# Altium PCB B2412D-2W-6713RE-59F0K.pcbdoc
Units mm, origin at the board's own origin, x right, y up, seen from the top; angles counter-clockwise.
Board outline 40 x 23 mm, 2 copper layers (Top Layer, Bottom Layer), stack 0.78 mm thick; 21 components, 12 nets, 48 pads, 26 vias.
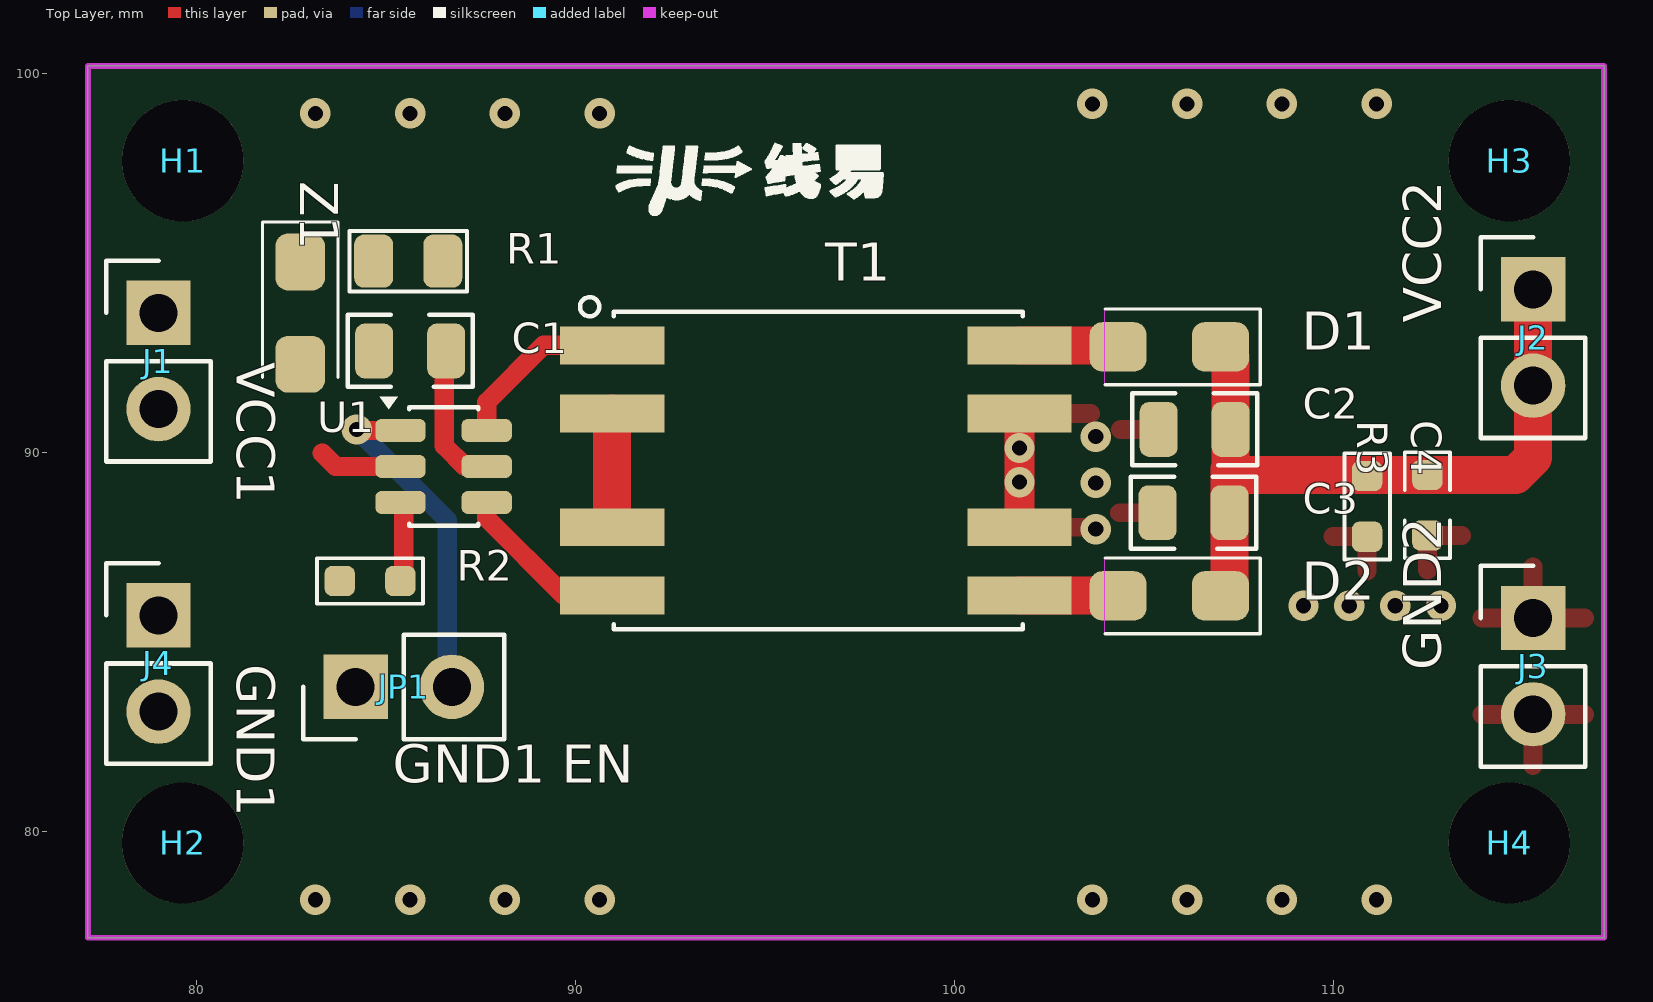
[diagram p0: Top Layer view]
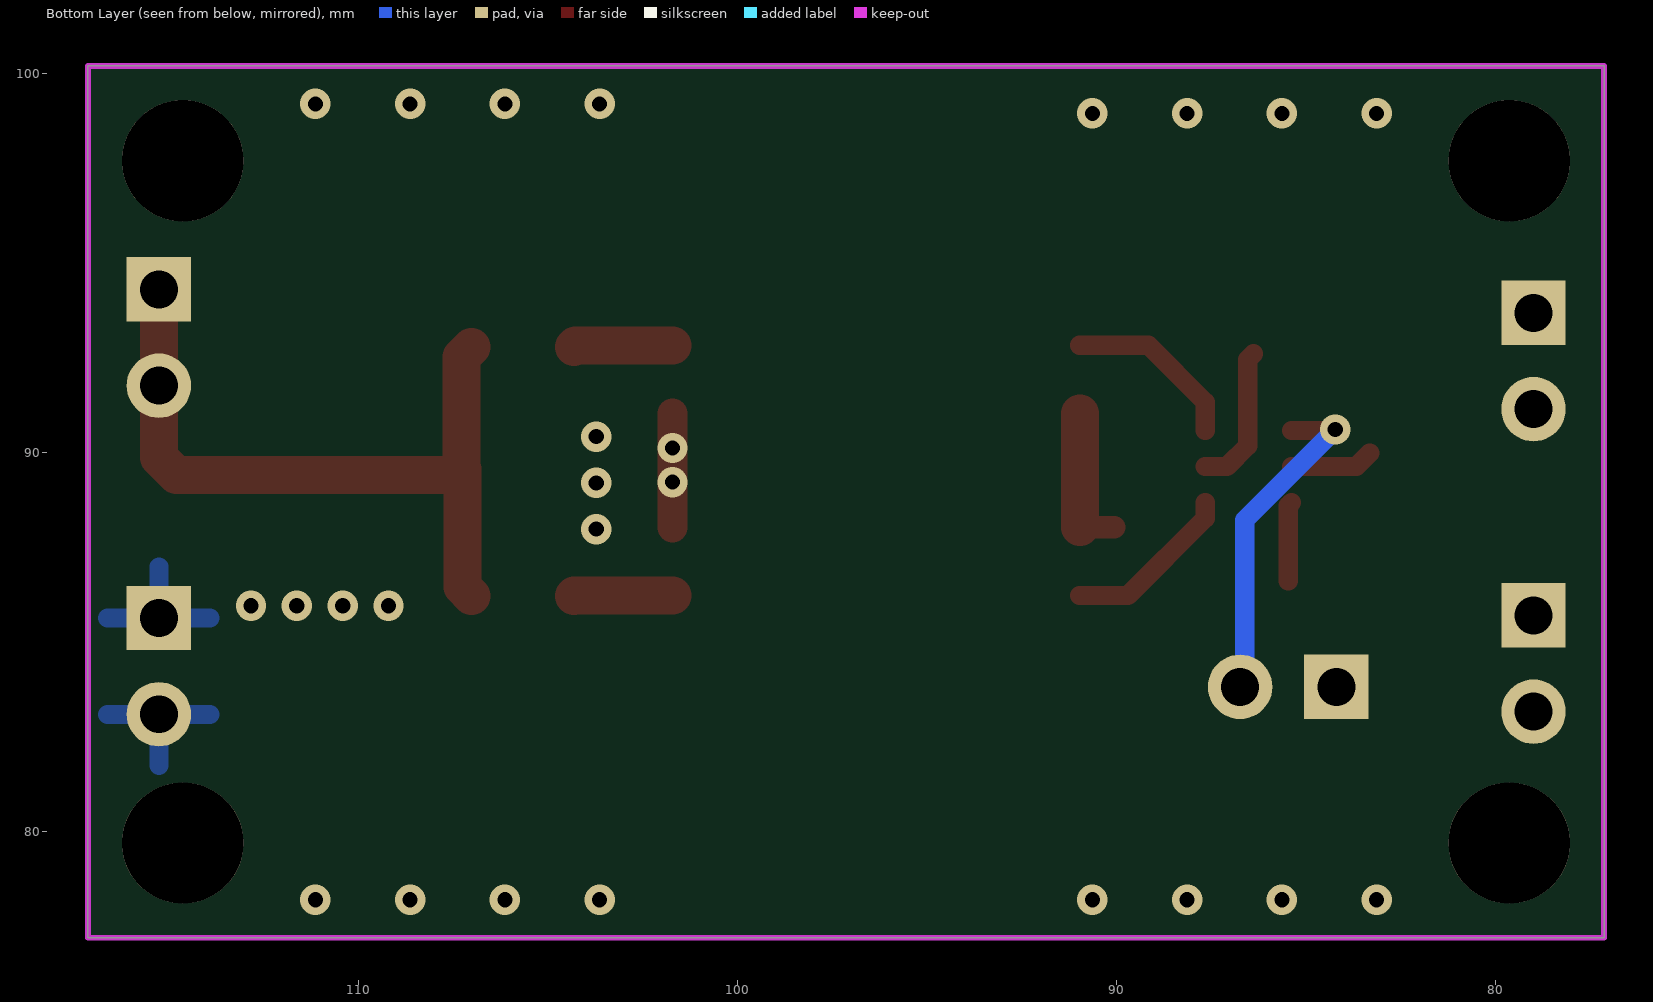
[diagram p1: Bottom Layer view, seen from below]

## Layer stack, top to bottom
Top Solder Mask Layer: solder mask 0.01, Dk 0
Top Layer: signal copper 0.035
dielectric 1: surface 0.71, FR4, Dk 4.5
Bottom Layer: signal copper 0.035
Bottom Solder Mask Layer: solder mask 0.01, Dk 0

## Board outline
117.15,100.2 117.15,77.2 77.15,77.2 77.15,100.2

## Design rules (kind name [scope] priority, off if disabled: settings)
BoardOutlineClearance copperThickness1oz [All] p0: genericclearance=0.254 ignorepadtopadclearanceinfootprint=FALSE except(0: Arc-SplitContinuation Track-SplitContinuation SMDPad-SplitContinuation THPad-SplitContinuation Via-SplitContinuation Fill-SplitContinuation Poly-SplitContinuation Region-SplitContinuation Text-SplitContinuation)
BoardOutlineClearance otherClearance [All] p0: genericclearance=0.254 ignorepadtopadclearanceinfootprint=FALSE except(0: Arc-SplitContinuation Track-SplitContinuation SMDPad-SplitContinuation THPad-SplitContinuation Via-SplitContinuation Fill-SplitContinuation Poly-SplitContinuation Region-SplitContinuation Text-SplitContinuation)
Clearance copperThickness1oz [All] p1: gap=0.178 ignorepadtopadclearanceinfootprint=FALSE
Clearance otherClearance [All] p1: gap=0.178 ignorepadtopadclearanceinfootprint=FALSE
DiffPairsRouting differentialPair [All] p1: maxuncoupledlength=10 minlimit=5 maxlimit=Infinity mostfreqgap=6 toplayer_minwidth=5 toplayer_prefwidth=100 toplayer_maxwidth=100 bottomlayer_minwidth=5 bottomlayer_prefwidth=100 bottomlayer_maxwidth=100
PasteMaskExpansion pasteMaskExpansion [All] p1: expansion=0
PlaneConnect innerPlane [All] p1: planeconnectstyle=Relief reliefexpansion=0.508 reliefentries=4 reliefconductorwidth=0.254 reliefairgap=0.254
PolygonConnect copper0 [All] p1: connectstyle=Direct reliefentries=4 reliefconductorwidth=10 polygonreliefangle="90 Angle" airgapwidth=10
PolygonConnect copper1 [All] p1: connectstyle=Relief reliefentries=4 reliefconductorwidth=19.685 polygonreliefangle="90 Angle" airgapwidth=19.685
RoutingVias viaSize [All] p1: viastyle="Through Hole" holewidth=24 minholewidth=11.811 maxholewidth=393.7 width=24 minwidth=11.811 maxwidth=393.7
SolderMaskExpansion solderMaskExpansion [IsVia] p1: useseparateexpansions=TRUE expansion=-1000 expansionbottom=-1000
SolderMaskExpansion solderMaskExpansion [All] p2: useseparateexpansions=TRUE expansion=2 expansionbottom=2
Width copperThickness1oz [All] p1: maxlimit=100 minlimit=5 preferedwidth=10

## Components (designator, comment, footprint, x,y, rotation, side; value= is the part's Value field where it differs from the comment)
C1 "10uF" C0805 85.65,92.68 r0 top
C2 "10uF" C0805 106.35,90.61 r0 top
C3 "My_Library_C" MYLibrary:C0805 106.32,88.412 r0 top
C4 "100nF" C0603 112.49,88.61 r90 top
D1 "B5819WS" SOD-323_L1.8-W1.3-LS2.5-RD 105.68,92.79 r180 top
D2 "B5819WS" SOD-323_L1.8-W1.3-LS2.5-RD 105.68,86.22 r180 top
H1 "Mechanical_MountingHole" MountingHole:MountingHole_3.2mm_M3 79.65,97.7 r0 top
H2 "Mechanical_MountingHole" MountingHole:MountingHole_3.2mm_M3 79.65,79.7 r0 top
H3 "Mechanical_MountingHole" MountingHole:MountingHole_3.2mm_M3 114.65,97.7 r0 top
H4 "Mechanical_MountingHole" MountingHole:MountingHole_3.2mm_M3 114.65,79.7 r0 top
J1 "HX PZ2.54-1x2P ZZ" HDR-TH_2P-P2.54-V-M-3 79.01,93.685 r0 top
J2 "HX PZ2.54-1x2P ZZ" HDR-TH_2P-P2.54-V-M-3 115.28,94.305 r0 top
J3 "HX PZ2.54-1x2P ZZ" HDR-TH_2P-P2.54-V-M-3 115.28,85.635 r0 top
J4 "HX PZ2.54-1x2P ZZ" HDR-TH_2P-P2.54-V-M-3 79.01,85.705 r0 top
JP1 "HX PZ2.54-1x2P ZZ" HDR-TH_2P-P2.54-V-M-3 84.211,83.819 r90 top
R1 "1Ω" R0805 85.6,95.05 r0 top
R2 "My_Library_R" MYLibrary:R0603 84.592,86.613 r0 top
R3 "10kΩ" R0603 110.9,88.58 r270 top
T1 "CMT59F0K" "My Library:CMT59F0K" 96.355,89.53 r0 top
U1 "CMP6713RE" "My Library:CMP6713RE" 86.532,89.633 r0 top
Z1 "SMF28CA" SOD-123FL_L2.8-W1.8-LS3.7-BI 82.75,93.68 r270 top

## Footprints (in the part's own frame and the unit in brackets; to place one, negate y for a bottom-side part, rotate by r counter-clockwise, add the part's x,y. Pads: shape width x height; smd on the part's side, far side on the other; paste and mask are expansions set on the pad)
C0603 [mm]
  rrect50% 0.8x0.8 smd paste+0 mask+0.05: 1(-0.8,0) 2(0.8,0)
  silkscreen extent -1.4,-0.6 1.4,0.6
C0805 [mm]
  rrect50% 1x1.45 smd paste+0 mask+0: 1(-0.95,0) 2(0.95,0)
  silkscreen extent -1.65,-0.95 1.65,0.96
HDR-TH_2P-P2.54-V-M-3 [mm]
  rect 1.7x1.7 hole 1 paste+0 mask+0: 1(0,0)
  round 1.7 hole 1 paste+0 mask+0: 2(0,-2.54)
  silkscreen extent -1.38,-3.92 1.38,1.38
MountingHole:MountingHole_3.2mm_M3 [mm]
  round 3.2 hole 3.2 unplated paste+0 mask+0: ""(0,0)
"My Library:CMP6713RE" [mm]
  rrect50% 1.325x0.6 smd paste+0 mask+0: 1(-1.138,0.95) 2(-1.138,0) 3(-1.138,-0.95) 4(1.137,-0.95) 5(1.137,0) 6(1.137,0.95)
  silkscreen extent -1.69,-1.56 0.91,1.84
"My Library:CMT59F0K" [mm]
  rect 2.75x1 smd paste+0 mask+0: 1(-5.375,3.3) 2(-5.375,1.5) 3(-5.375,-1.5) 4(-5.375,-3.3) 5(5.375,-3.3) 6(5.375,-1.5) 7(5.375,1.5) 8(5.375,3.3)
  silkscreen extent -6.22,-4.19 5.46,4.57
MYLibrary:C0805 [mm]
  rrect50% 1x1.45 smd paste+0 mask+0: 1(-0.95,0) 2(0.95,0)
  silkscreen extent -1.65,-0.95 1.65,0.96
MYLibrary:R0603 [mm]
  rrect50% 0.8x0.8 smd paste+0 mask+0.05: 1(-0.8,0) 2(0.8,0)
  silkscreen extent -1.4,-0.6 1.4,0.6
R0603 [mm]
  rrect50% 0.8x0.8 smd paste+0 mask+0.05: 1(-0.8,0) 2(0.8,0)
  silkscreen extent -1.4,-0.6 1.4,0.6
R0805 [mm]
  rrect48% 1.025x1.4 smd paste+0 mask+0: 1(-0.913,0) 2(0.913,0)
  silkscreen extent -1.55,-0.8 1.55,0.8
SOD-123FL_L2.8-W1.8-LS3.7-BI [mm]
  rrect50% 1.5x1.3 smd paste+0 mask+0: 1(-1.35,0) 2(1.35,0)
  silkscreen extent -2.4,-1 1.7,1
SOD-323_L1.8-W1.3-LS2.5-RD [mm]
  rrect50% 1.5x1.3 smd paste+0 mask+0: 1(-1.35,0) 2(1.35,0)
  silkscreen extent -2.4,-1 1.7,1

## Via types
v1: diameter 0.8, hole 0.4, Top Layer to Bottom Layer, 26 vias

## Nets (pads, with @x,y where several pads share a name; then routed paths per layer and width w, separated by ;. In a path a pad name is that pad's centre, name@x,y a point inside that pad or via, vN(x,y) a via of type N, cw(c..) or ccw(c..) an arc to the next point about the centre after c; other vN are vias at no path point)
$1N6: C1.2 R1.2 U1.5 | length 3.8
  Top Layer w0.508: C1.2@86.4,92.61 86.552,92.457 86.552,90.178 87.098,89.633 U1.5
$1N7: T1.1 U1.6 | length 4.7
  Top Layer w0.508: U1.6 87.67,91.33 89.17,92.83 T1.1
$1N9: T1.4 U1.4 | length 4.6
  Top Layer w0.508: U1.4 87.67,88.27 89.71,86.23 T1.4
$1N10: T1.2 T1.3 | length 3.9
  Top Layer w0.6: T1.3@90.075,88.03 T1.3
  Top Layer w1: T1.3 T1.2
$1N11: D2.2 T1.5 | length 2.6
  Top Layer w1: T1.5 104.32,86.23 D2.2
$1N13: D1.2 T1.8 | length 2.6
  Top Layer w1: T1.8 104.29,92.83 D1.2
CLK: R2.2 U1.3 | length 2.1
  Top Layer w0.508: U1.3 85.48,88.598 R2.2@85.48,86.61
EN: JP1.2 U1.1 | length 8.9
  Top Layer w0.508: v1(84.24,90.61) 84.267,90.583 U1.1
  Bottom Layer w0.508: v1(84.24,90.61) 86.63,88.22 86.63,83.965 JP1.2@86.735,83.86
GND1: C1.1 J4.1 J4.2 JP1.1 R2.1 U1.2 Z1.2 | length 2.2
  Top Layer w0.508: 83.33,89.99 83.687,89.633 U1.2
  other v1: 83.15,78.2 85.65,78.2 88.15,78.2 90.65,78.2 83.15,98.95 85.65,98.95 88.15,98.95 90.65,98.95
GND2: C2.1 C3.1 C4.1 J3.1 J3.2 R3.2 T1.6 T1.7 | length 3
  Top Layer w0.8: T1.6 v1(101.73,89.22) v1(101.73,90.12) T1.7
  other v1: 103.65,78.2 106.15,78.2 108.65,78.2 111.15,78.2 109.22,85.96 110.43,85.96 111.64,85.96 112.85,85.96 103.74,87.98 103.74,89.2 103.74,90.42 103.65,99.2 106.15,99.2 108.65,99.2 111.15,99.2
VCC1: J1.1 J1.2 R1.1 Z1.1
VCC2: C2.2 C3.2 C4.2 D1.1 D2.1 J2.1 J2.2 R3.1 | length 19.5
  Top Layer w1: D2.1 107.27,86.46 C3.2 107.27,89.56 107.3,89.59 ; D1.1 107.3,92.52 C2.2 107.3,89.59 ; J2.1 J2.2 115.28,89.87 114.82,89.41 C4.2 107.48,89.41 107.3,89.59
pads on no net: H1. H2. H3. H4.

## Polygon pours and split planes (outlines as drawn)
$1N6 on Top Layer (solid, remove dead copper, pour order 2): 85.709,95.895 87.209,95.895 87.209,91.885 85.709,91.885
VCC1 on Top Layer (solid, remove dead copper, pour order 4): 77.67,89.78 77.67,95.75 85.2,95.75 85.2,94.45 84.98,94.23 81.5,94.23 81.45,94.28 80.76,93.59 80.76,89.84 80.79,89.81 80.78,89.8 77.68,89.8 77.68,89.79
GND1 on Top Layer (solid, remove dead copper, pour order 6): 77.17,101.225 92.355,101.225 92.355,76.225 77.17,76.225
GND1 on Bottom Layer (solid, remove dead copper, pour order 16): 77.17,101.225 92.355,101.225 92.355,76.225 77.17,76.225
GND2 on Top Layer (solid, remove dead copper, pour order 10): 100.43,101.2 122.2,101.2 122.2,76.2 100.43,76.2
GND2 on Bottom Layer (solid, remove dead copper, pour order 20): 100.43,101.2 122.2,101.2 122.2,76.2 100.43,76.2

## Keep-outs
Top Layer:
  region: 103.98,93.79 108.08,93.79 108.08,91.79 103.98,91.79
  region: 103.98,87.22 108.08,87.22 108.08,85.22 103.98,85.22
Board Outline Layer:
  the board outline again, w0.15

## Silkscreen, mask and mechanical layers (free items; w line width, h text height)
Top Silkscreen Layer:
  drawing of 9 lines, arcs and shapes, not listed
  text "VCC2" at 112.86,93.43 h1 r90
  text "VCC1" at 81.07,92.38 h1 r270
  text "GND1" at 81.07,84.41 h1 r270
  text "GND2" at 112.86,84.26 h1 r90
  text "GND1 EN" at 85.186,81.29 h1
